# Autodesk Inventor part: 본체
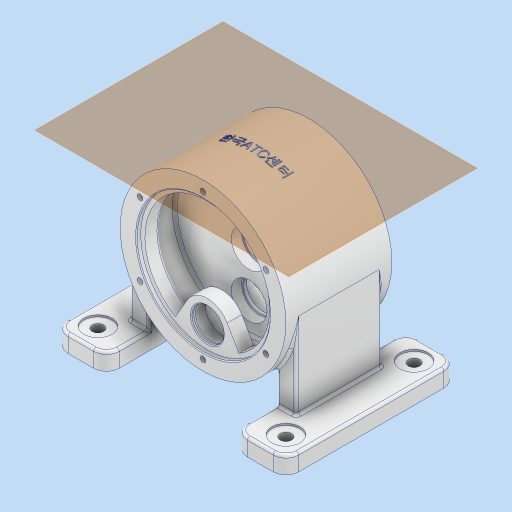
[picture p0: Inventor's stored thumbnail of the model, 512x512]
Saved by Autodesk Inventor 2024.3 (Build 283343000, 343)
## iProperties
Created: 2025-12
Part Number: 본체
Material: 알루미늄 6061
Document SubType Name: Modeling
Designer: PC2-03
Density: 2.7 g/cm^3
Appearance: 알루미늄 - 평지
Mass: 5636.71 g
Surface Area: 3068.86 cm^2
Volume: 2087.67 cm^3
Author: PC2-03
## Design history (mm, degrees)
sketch "스케치1"
  geometry: L1 (-97, 0)-(-97, -100); L2 (-97, -100)-(-135, -100); L3 (-135, -100)-(-135, -120); L4 (-135, -120)-(-75, -120); L5 (-75, -120)-(-75, -61.514); L6 (0, 0)-(0, -175.176); L7 (97, 0)-(97, -100); L8 (97, -100)-(135, -100); L9 (135, -100)-(135, -120); L10 (135, -120)-(75, -120); L11 (75, -120)-(75, -61.514); L12 (-36.6, -89.83)-(-75, -112); L13 (36.6, -89.83)-(75, -112); L14 (97, -100)-(75, -100); L15 (-97, -100)-(-75, -100); A1 r 97 centre (0, 0) between (-97, 0) and (-75, -61.514); 5 further points
  constraints: 30 end point, 8 symmetric about line, 4 perpendicular, 4 point on line, 3 point on circle, 2 vertical, 1 centre point, 1 coincident, 1 horizontal
  dimensions: "d0" = 194 diameter of A1; "d1" = 120 distance from line of L10 L6.start; "d2" = 8 distance of L12.end L4.end; "d3" = 60 deg angle of L5 L12; "d4" = 22 distance between parallel lines of L7 L11; "d5" = 20 distance between parallel lines of L4 L2; "d6" = 60 distance of L9.end L10.end
extrude "돌출1" new body sketch "스케치1" stored distance "d8" = 124; taper "d9" = 0 deg
extrude "돌출2" join sketch "스케치1" stored distance "d10" = 100; taper "d11" = 0 deg
extrude "돌출3" join sketch "스케치1" stored distance "d12" = 200; taper "d13" = 0 deg
extrude "돌출4" join sketch "스케치1" stored distance "d14" = 12; taper "d15" = 0 deg
sketch "스케치2"
  geometry: L1 (84, -40)-(76, -40); L2 (73, -57)-(78, -57); L3 (97, 62)-(-97, 62) reference; L4 (-97, -62)-(97, -62) reference; L5 (-61.514, 6)-(-89.83, 6) reference; L6 (-89.83, 6)-(-89.83, -6) reference; L7 (-89.83, -6)-(-61.514, -6) reference; L8 (-61.514, -6)-(-61.514, -50) reference; L9 (-61.514, -50)-(0, -50) reference; L10 (0, -50)-(0, 50) reference; L11 (0, 50)-(-61.514, 50) reference; L12 (-61.514, 50)-(-61.514, 6) reference; L13 (-89.83, 6)-(-61.514, 6) reference; L14 (-61.514, 6)-(-61.514, 50) reference; L15 (-61.514, 50)-(0, 50) reference; L16 (0, -50)-(0, 50) reference; L17 (0, -50)-(-61.514, -50) reference; L18 (-61.514, -50)-(-61.514, -6) reference; L19 (-61.514, -6)-(-89.83, -6) reference; L20 (-89.83, -6)-(-89.83, 6) reference; L21 (78, -57)-(78, -62); L22 (0, 0)-(0, -89.871); L23 (87, -37)-(87, -11); L24 (84, -8)-(0, -8); L25 (73, -57)-(73, -43); A1 r 3 centre (84, -11) between (87, -11) and (84, -8); A2 r 3 centre (84, -37) between (84, -40) and (87, -37); A3 r 3 centre (76, -43) between (76, -40) and (73, -43); 4 further points
  constraints: 14 end point, 6 point on circle, 5 tangent, 4 point on line, 3 centre point, 3 vertical, 2 perpendicular, 1 equal radius
  dimensions: "d18" = 156 diameter of L21 L22; "d21" = 32 distance between parallel lines of L24 L1; "d22" = 22 distance between parallel lines of L4 L1; "d23" = 5 distance between parallel lines of L4 L2; "d24" = 174 diameter of L23 L22; "d25" = 3 radius of A1; "d37" = 146 diameter of L25 L22; "d38" = 3 radius of A3 (derived)
revolve "회전1" sketch "스케치2" stored, may be unused: angle "d28" = 90 deg
sketch "스케치3"
  geometry: L1 (0, 8)-(84, 8); L2 (87, 11)-(87, 37); L3 (84, 40)-(76, 40); L4 (73, 43)-(73, 57); L5 (73, 57)-(78, 57); L6 (97, 62)-(-97, 62) reference; L7 (-97, -62)-(97, -62) reference; L8 (-61.514, 6)-(-89.83, 6) reference; L9 (-89.83, 6)-(-89.83, -6) reference; L10 (-89.83, -6)-(-61.514, -6) reference; L11 (-61.514, -6)-(-61.514, -50) reference; L12 (-61.514, -50)-(0, -50) reference; L13 (0, -50)-(0, 50) reference; L14 (0, 50)-(-61.514, 50) reference; L15 (-61.514, 50)-(-61.514, 6) reference; L16 (-89.83, 6)-(-61.514, 6) reference; L17 (-61.514, 6)-(-61.514, 50) reference; L18 (-61.514, 50)-(0, 50) reference; L19 (0, -50)-(0, 50) reference; L20 (0, -50)-(-61.514, -50) reference; L21 (-61.514, -50)-(-61.514, -6) reference; L22 (-61.514, -6)-(-89.83, -6) reference; L23 (-89.83, -6)-(-89.83, 6) reference; L24 (78, 57)-(78, 62); L25 (0, 0)-(0, 115.869); A1 r 3 centre (84, 11) between (84, 8) and (87, 11); A2 r 3 centre (84, 37) between (87, 37) and (84, 40); A3 r 3 centre (76, 43) between (73, 43) and (76, 40); 3 further points
  constraints: 14 end point, 6 point on circle, 6 tangent, 4 perpendicular, 3 centre point, 2 equal radius, 2 point on line, 1 horizontal, 1 vertical
  dimensions: "d30" = 174 diameter of L2 L25; "d31" = 146 diameter of L4 L25; "d32" = 156 diameter of L24 L25; "d33" = 32 distance between parallel lines of L3 L1; "d34" = 22 distance between parallel lines of L3 L6; "d35" = 5 distance between parallel lines of L5 L6; "d36" = 3 radius of A1 (derived)
revolve "회전2" sketch "스케치3" stored, may be unused: angle "d39" = 90 deg
chamfer "모따기1" distance "d40" = 1; stored, may be unused: second distance "d41" = 2, angle "d42" = 45 deg
sketch "스케치5"
  geometry: L1 (0, 102.077)-(0, -102.077); L2 (97, 62)-(-97, 62) reference; L3 (-97, -62)-(97, -62) reference; L4 (-61.514, 6)-(-89.83, 6) reference; L5 (-89.83, 6)-(-89.83, -6) reference; L6 (-89.83, -6)-(-61.514, -6) reference; L7 (-61.514, -6)-(-61.514, -50) reference; L8 (-61.514, -50)-(0, -50) reference; L9 (0, -50)-(0, 50) reference; L10 (0, 50)-(-61.514, 50) reference; L11 (-61.514, 50)-(-61.514, 6) reference; L12 (-89.83, 6)-(-61.514, 6) reference; L13 (-61.514, 6)-(-61.514, 50) reference; L14 (-61.514, 50)-(0, 50) reference; L15 (0, -50)-(0, 50) reference; L16 (0, -50)-(-61.514, -50) reference; L17 (-61.514, -50)-(-61.514, -6) reference; L18 (-61.514, -6)-(-89.83, -6) reference; L19 (-89.83, -6)-(-89.83, 6) reference; L20 (-84, 8)-(84, 8) reference; L21 (84, -8)-(-84, -8) reference; L22 (0, 8)-(21, 8); L23 (21, 8)-(21, -4); L24 (21, -4)-(0, -4); L25 (0, -4)-(0, 8); L26 (0, -4)-(19, -4); L27 (19, -4)-(19, -8); L28 (19, -8)-(0, -8); L29 (0, -8)-(0, -4); L30 (-52.5, -102.077)-(-52.5, 100.523); L31 (-52.5, 8)-(-31.5, 8); L32 (-31.5, 8)-(-31.5, -4); L33 (-31.5, -4)-(-52.5, -4); L34 (-52.5, -4)-(-52.5, 8); L35 (-52.5, -4)-(-33.5, -4); L36 (-33.5, -4)-(-33.5, -8); L37 (-33.5, -8)-(-52.5, -8); L38 (-52.5, -8)-(-52.5, -4); 9 further points
  constraints: 36 end point, 8 parallel, 4 horizontal, 4 perpendicular, 4 point on line, 3 midpoint, 2 vertical
  dimensions: "d43" = 42 diameter of L23 L1; "d44" = 38 diameter of L27 L1; "d45" = 66 distance between parallel lines of L2 L26; "d46" = 52.5 distance between parallel lines of L30 L1; "d47" = 42 diameter of L32 L30; "d48" = 38 diameter of L36 L30; "d49" = 66 distance between parallel lines of L2 L33
  node "투영된 루프3"
revolve "회전3" stored, may be unused: angle "d50" = 90 deg
revolve "회전4" stored, may be unused: angle "d51" = 90 deg
sketch "스케치6"
  geometry: L1 (-23.383, -39)-(-37.148, -62.842); L2 (23.383, -39)-(37.148, -62.842); L3 (0, 0)-(0, -122.493); C1 r 19 at (0, -52.5) reference; A1 r 27 centre (0, -52.5) between (-23.383, -39) and (23.383, -39); A2 r 73 centre (0, 0) between (-37.148, -62.842) and (37.148, -62.842) reference; 1 further point
  constraints: 6 end point, 4 point on circle, 2 tangent, 1 centre point, 1 coincident, 1 vertical
  dimensions: "d52" = 54 diameter of A1; "d53" = 30 deg angle of L2 L3; "d54" = 30 deg angle of L3 L1
extrude "돌출5" join sketch "스케치6" distance "d55" = 17; taper "d56" = 0 deg
sketch "스케치7"
  geometry: L1 (-39, 57)-(-39, 57) reference; L2 (-39, 57)-(-39, 40) reference; L3 (-39, 40)-(-39, 40) reference; L4 (-39, 57)-(-39, 40) reference; L5 (97, 62)-(-97, 62) reference; L6 (-97, -62)-(97, -62) reference; L7 (-61.514, 6)-(-89.83, 6) reference; L8 (-89.83, 6)-(-89.83, -6) reference; L9 (-89.83, -6)-(-61.514, -6) reference; L10 (-61.514, -6)-(-61.514, -50) reference; L11 (-61.514, -50)-(0, -50) reference; L12 (0, -50)-(0, 50) reference; L13 (0, 50)-(-61.514, 50) reference; L14 (-61.514, 50)-(-61.514, 6) reference; L15 (-89.83, 6)-(-61.514, 6) reference; L16 (-61.514, 6)-(-61.514, 50) reference; L17 (-61.514, 50)-(0, 50) reference; L18 (0, -50)-(0, 50) reference; L19 (0, -50)-(-61.514, -50) reference; L20 (-61.514, -50)-(-61.514, -6) reference; L21 (-61.514, -6)-(-89.83, -6) reference; L22 (-89.83, -6)-(-89.83, 6) reference; L23 (-71.5, 57)-(-33.5, 57) reference; L24 (-33.5, 40)-(-33.5, 57) reference; L25 (-33.5, 52)-(-30.25, 52); L26 (-30.25, 52)-(-30.25, 53.95); L27 (-30.25, 53.95)-(-33.5, 53.95); L28 (-33.5, 46.063)-(-33.5, 70.343); L29 (-52.5, 50)-(-52.5, 71.484); L30 (-33.5, 40)-(-71.5, 40) reference; 1 further point
  constraints: 10 end point, 5 point on line, 2 perpendicular, 1 horizontal, 1 vertical
  dimensions: "d57" = 1.95 distance between parallel lines of L25 L27; "d58" = 44.5 diameter of L26 L29; "d59" = 12 distance between parallel lines of L30 L25
revolve "회전5" sketch "스케치7" stored, may be unused: angle "d60" = 90 deg
fillet "모깎기1" dims "d62" = 0.6
chamfer "모따기2" distance "d63" = 1; stored, may be unused: second distance "d64" = 2, angle "d65" = 45 deg
sketch "스케치10" dims "d66" = 170
  geometry: C1 r 87 at (0, 0) reference; C2 r 84 at (0, 0) reference; 3 further points
  constraints: 1 coincident, 1 vertical alignment, 2 other
hole "구멍1" sketch "스케치10" at (0, 85) diameter "d67" = 6.647; stored, may be unused: countersink angle "d71" = 90 deg, drill point angle "d73" = 118 deg; dims "d68" = 16, "d69" = 8, "d70" = 4.4, "d72" = 18
fillet "모깎기2" dims "d77" = 15
fillet "모깎기3" dims "d78" = 3
fillet "모깎기4" dims "d79" = 3
fillet "모깎기5" dims "d80" = 3
fillet "모깎기6" dims "d81" = 3
fillet "모깎기7" dims "d82" = 3
sketch "스케치11"
  geometry: L1 (-184, 44)-(-168, 44) reference; L2 (-190, 144)-(-190, 50) reference; L3 (-168, 150)-(-184, 150) reference; L4 (-168, 182)-(-168, 150) reference; L5 (-210, 194)-(-180, 194) reference; L6 (-222, 12)-(-222, 182) reference; L7 (-180, 0)-(-210, 0) reference; L8 (-168, 44)-(-168, 12) reference; L9 (4, 150)-(-12, 150) reference; L10 (10, 50)-(10, 144) reference; L11 (-12, 44)-(4, 44) reference; L12 (-12, 12)-(-12, 44) reference; L13 (30, 0)-(0, 0) reference; L14 (42, 182)-(42, 12) reference; L15 (0, 194)-(30, 194) reference; L16 (-12, 150)-(-12, 182) reference; L17 (-69, 89)-(-111, 89) reference; L18 (-225, 182)-(-225, 12) reference; L19 (-210, -3)-(-180, -3) reference; L20 (-225, 182)-(-225, 12) reference; L21 (-225, 97)-(-225, 22); L22 (-225, 22)-(-200, 22); L23 (-200, 22)-(-200, -39.546); A1 r 6 centre (-184, 50) between (-190, 50) and (-184, 44) reference; A2 r 6 centre (-184, 144) between (-184, 150) and (-190, 144) reference; A3 r 12 centre (-180, 182) between (-168, 182) and (-180, 194) reference; A4 r 12 centre (-210, 182) between (-210, 194) and (-222, 182) reference; A5 r 12 centre (-210, 12) between (-222, 12) and (-210, 0) reference; A6 r 12 centre (-180, 12) between (-180, 0) and (-168, 12) reference; A7 r 6 centre (4, 144) between (10, 144) and (4, 150) reference; A8 r 6 centre (4, 50) between (4, 44) and (10, 50) reference; A9 r 12 centre (0, 12) between (-12, 12) and (0, 0) reference; A10 r 12 centre (30, 12) between (30, 0) and (42, 12) reference; A11 r 12 centre (30, 182) between (42, 182) and (30, 194) reference; A12 r 12 centre (0, 182) between (0, 194) and (-12, 182) reference; A13 r 12 centre (-210, 12) between (-222, 12) and (-210, 0) reference; A14 r 15 centre (-210, 12) between (-225, 12) and (-210, -3) reference; 3 further points
  constraints: 6 end point, 1 coincident, 1 midpoint, 1 perpendicular, 1 point on line, 1 vertical
  dimensions: "d86" = 75 distance of L21.start L21.end; "d87" = 25 distance of L21.end L22.end; "d88" = 150 distance of point (-200, 22) point (-200, 172)
hole "구멍2" sketch "스케치11" at (-200, 22), (-200, 172) diameter "d89" = 13.5; stored, may be unused: countersink angle "d93" = 90 deg, drill point angle "d95" = 118 deg; dims "d90" = 16, "d91" = 33, "d92" = 2, "d94" = 20
node "작업 평면1"
sketch "스케치12"
  geometry: L1 (-97, -62)-(97, -62) reference; 2 further points
  constraints: 1 coincident, 1 other
feature "엠보싱1" sketch "스케치12" dims "d0" = 194, "d1" = 120, "d2" = 8, "d3" = 60 deg, "d4" = 22, "d5" = 20, "d6" = 60, "d96" = 0.5, "d97" = 0
node "솔리드1"
pattern_circular "원형 패턴1" dims angle "d75" = 360 deg
mirror "미러1"
mirror "미러2"
node "투영된 루프1"
node "투영된 루프2"
node "투영된 루프4"
node "투영된 루프5"
node "투영된 루프6"
node "투영된 루프7"
feature "A9D066F2-1C7D-4E18-AEED-F7BC21143FA4" dims "d89" = 13.5, "d90" = 16, "d91" = 33, "d92" = 2, "d93" = 90 deg, "d94" = 20, "d95" = 118 deg
